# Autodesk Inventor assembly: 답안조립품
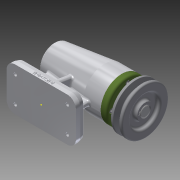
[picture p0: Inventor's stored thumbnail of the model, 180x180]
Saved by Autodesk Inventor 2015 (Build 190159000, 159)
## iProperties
Created: 2017-01
Part Number: 답안조립품
Document SubType Name: Assembly
Designer: Administrator
Author: Administrator
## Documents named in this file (12)
- C:\Users\Administrator\Desktop\470107V1018\답안조립품.iam
- C:\Users\Administrator\Desktop\470107V1018\본체.ipt
- C:\Users\Administrator\Desktop\470107V1018\멈춤나사 M3x8.ipt
- C:\Users\Administrator\Desktop\470107V1018\베어링 6004.ipt
- C:\Users\Administrator\Desktop\470107V1018\베어링 51202.ipt
- C:\Users\Administrator\Desktop\470107V1018\볼트 M4 x 12.ipt
- C:\Users\Administrator\Desktop\470107V1018\어댑터슬리브.ipt
- C:\Users\Administrator\Desktop\470107V1018\오일 실.ipt
- C:\Users\Administrator\Desktop\470107V1018\축.ipt
- C:\Users\Administrator\Desktop\470107V1018\커버.ipt
- C:\Users\Administrator\Desktop\470107V1018\키 5 x 5 x 16.ipt
- C:\Users\Administrator\Desktop\470107V1018\V벨트풀리.ipt
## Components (6 placed, 2 different names)
1. ISO 4762 M4 x 12:1
2. V벨트풀리:1 — 각도:2
3. ISO 4762 M4 x 12:2
4. ISO 4762 M4 x 12:3
5. ISO 4762 M4 x 12:4
6. ISO 4762 M4 x 12:5
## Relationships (1: Angle 1)
- 각도:2 [Angle]: V벨트풀리:1
